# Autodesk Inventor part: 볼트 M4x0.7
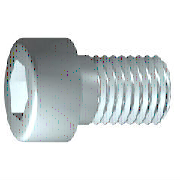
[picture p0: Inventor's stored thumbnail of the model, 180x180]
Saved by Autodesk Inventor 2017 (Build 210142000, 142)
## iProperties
IsCustomPart: 0
Created: 2015-12
Part Number: 볼트 M4x0.7
Material: 강철, 연강
Description: 6각머리 태핑 나사
Document SubType Name: Modeling
Standard: KS B 1003
Designer: mdu
Standards Organization: KS
Language: ko-KR
Size Designation: M 4 x 12
Categories: <MemberInstance><Categories><Category DisplayName="조임쇠" InternalName="e4da775c-781d-43d5-af7c-5136215cf5a6" Mnemonic="FSTN"><Category DisplayName="볼트" InternalN
Density: 7.86 g/cm^3
Appearance: 강철
Mass: 2.23465 g
Surface Area: 3.30853 cm^2
Volume: 0.284306 cm^3
Author: mdu
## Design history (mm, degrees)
sketch "스케치1"
  geometry: L1 (-1, 0)-(12, 0); L2 (12, 0)-(12, 2); L3 (12, 2)-(1.75, 2); L4 (1.75, 2)-(1.32, 2); L5 (1.32, 2)-(0, 2); L6 (0, 2)-(0, 3.5); L7 (0, 3.5)-(-4, 3.5); L8 (-4, 3.5)-(-4, 1.732); L9 (-4, 1.732)-(-2, 1.732); L10 (-2, 1.732)-(-1, 0); L11 (-7.2, 0)-(15.2, 0) reference; L12 (0, -0.7)-(0, 4.2) reference; L13 (1.75, 2)-(0, 2)
  constraints: 22 end point, 6 parallel, 2 collinear, 2 perpendicular, 1 horizontal, 1 point on line
  dimensions: "d1" = 10.25 distance from line of L3.end L2 (= GEL); "d2" = 0.42952 distance of L4.end L3.end (computed from GAL); "d3" = 4 distance between parallel lines of L8 L6 (= KOH); "d4" = 2 distance of L8.end L9.end (= INTI); "d5" = 60 deg angle of L10 L1; "d6" = 4 diameter of L3 L1 (= GD); "d7" = 4 diameter of L5 L1 (= BDM); "d8" = 3.4641 diameter of L9 L1 (= 1.1547 x SW); "d9" = 7 diameter of L7 L1 (= KOD); "d26" = 12 distance between parallel lines of L12 L2 (= NLG)
revolve "본체" sketch "스케치1" stored, may be unused: angle "d10" = 90 deg
sketch "스케치2"
  geometry: L1 (0, -4.9)-(0, 4.9) reference; L2 (-4.9, 0)-(4.9, 0) reference; L3 (1.732, 0)-(0.866, -1.5); L4 (0.866, -1.5)-(-0.866, -1.5); L5 (-0.866, -1.5)-(-1.732, 0); L6 (-1.732, 0)-(-0.866, 1.5); L7 (-0.866, 1.5)-(0.866, 1.5); L8 (0.866, 1.5)-(1.732, 0); 2 further points
  constraints: 12 end point, 1 coincident, 1 horizontal alignment, 1 point on line, 12 other
extrude "슬롯" join sketch "스케치2" stored distance "d11" = 10; taper "d12" = 0 deg
workplane "Work Plane1"
fillet "Fillet2" dims "d30" = 0.1 (= R)
body "Solid1"
fillet "모깎기1" dims "d17" = 0.4 (= RR)
feature "스레드" dims "d13" = 10.25 (= GEL), "d14" = 0
chamfer "모따기1" distance "d15" = 0.42941 (= -0.5 x SPD + 0.5 x GD); stored, may be unused: second distance "d16" = 0.42941 (= GUL), angle "d27" = 45 deg
other parameters: "GD" = 4 (= NND) [user parameter; used in 2 equation terms], "NLG" = 12 [user parameter; used in 1 equation term], "GEL" = 10.25 [user parameter; used in 2 equation terms], "KOD" = 7 [user parameter; used in 1 equation term], "KOH" = 4 [user parameter; used in 1 equation term], "INTI" = 2 [user parameter; used in 1 equation term], "GAL" = 0.42941 (= 0.61345 x PTC) [user parameter; used in 1 equation term], "GUL" = 0.42941 (= 0.61345 x PTC) [user parameter; used in 1 equation term], "BDM" = 4 (= NND) [user parameter; used in 1 equation term], "SW" = 3 [user parameter; used in 2 equation terms], "RR" = 0.4 [user parameter; used in 1 equation term], "SPD" = 3.14117 (= NND - 1.2269 x PTC) [user parameter; used in 1 equation term], "d19" = 0, "d28" = 0, "d29" = 0, "R" = 0.1 [user parameter; used in 1 equation term], "PHH" = 0.2 [user parameter], "GD1" = 3.14117 (= THREADDIA - 1.2269 x PTC) [user parameter], "THREADDIA" = 4 [user parameter; used in 1 equation term], "FAWI" = 45 deg [user parameter], "TPU" = 14.28571 (computed from PTC) [user parameter], "PTC" = 0.7 [user parameter; used in 5 equation terms], "NND" = 4 [user parameter; used in 3 equation terms], "TOA" = 30 deg [user parameter], "E0" = 3.465 (= 1.155 x SW) [user parameter]
